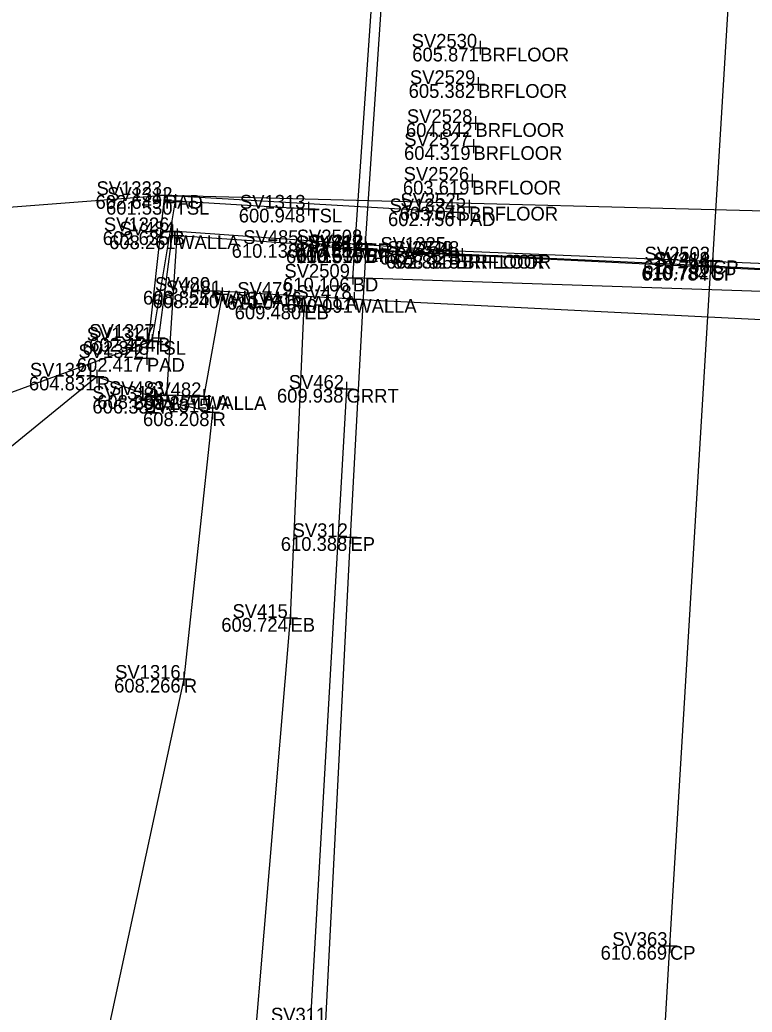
# Model space of a CAD drawing. Extents: x -2 to 1979875, y -2 to 232027.
# Drawn here: x 1978749.24 to 1978775.86, y 231225.36 to 231261.41 of the extents above; entities that cross this region are included whole.
import ezdxf

# ---------------------------------------------------------------- set-up
doc = ezdxf.new("R2010")
doc.units = 0
for name, color, linetype in [('_CIVIL_CONSTRUCTION', 7, 'Continuous'), ('BR_X_SV_Abut', 7, 'Continuous'), ('BR_X_SV_Deck_Floor_Text', 7, 'Continuous'), ('BR_X_SV_Deck_Top', 7, 'Continuous'), ('BR_X_SV_Deck_Top_Text', 7, 'Continuous'), ('DR_X_Erosion_Control', 7, 'Continuous'), ('GE_P_Alignment', 7, 'Continuous'), ('GE_P_Alignment_1000_Stations', 7, 'Continuous'), ('GE_P_Alignment_500_Stations', 7, 'Continuous'), ('GE_X_Alignment', 7, 'Continuous'), ('GE_X_Alignment_1000_Curve_Data', 7, 'Continuous'), ('GE_X_Alignment_1000_Stations', 7, 'Continuous'), ('GE_X_Alignment_100_Curve_Data', 7, 'Continuous'), ('GE_X_Alignment_100_Stations', 7, 'Continuous'), ('HY_X_Water_Edge', 7, 'Continuous'), ('RD_X_Concrete_Pad', 7, 'Continuous'), ('SC_Scratch1', 7, 'Continuous'), ('SV_X_Toe_of_Slope', 7, 'Continuous')]:
    doc.layers.add(name, color=color, linetype=linetype)

msp = doc.modelspace()

# ---------------------------------------------------------------- linework, layer by layer
at = {"layer": 'BR_X_SV_Abut'}
for p, q in [((1978761.383, 231253.071), (1978785.768, 231251.859)), ((1978761.397, 231251.268), (1978785.698, 231250.046))]:
    msp.add_line(p, q, dxfattribs=at)
msp.add_lwpolyline([(1978761.397, 231251.268), (1978759.239, 231251.381), (1978756.252, 231251.566), (1978756.595, 231251.439), (1978755.933, 231247.737), (1978754.58, 231247.78), (1978754.956, 231253.581), (1978759.469, 231253.268), (1978761.383, 231253.071)], dxfattribs=at)
at = {"layer": 'BR_X_SV_Deck_Top'}
msp.add_lwpolyline([(1978761.339, 231252.043), (1978764.257, 231294.289), (1978788.348, 231293.277), (1978785.624, 231251.227)], close=True, dxfattribs=at)
at = {"layer": 'DR_X_Erosion_Control'}
msp.add_lwpolyline([(1978754.349, 231247.608), (1978756.246, 231247.151), (1978755.199, 231237.468), (1978752.104, 231223.077), (1978746.455, 231220.249), (1978747.402, 231233.48), (1978747.083, 231244.422), (1978752.039, 231248.449)], close=True, dxfattribs=at)
at = {"layer": 'GE_P_Alignment'}
msp.add_line((1978782.12, 231252.312), (1978764.845, 231253.02), dxfattribs=at)
for points in [[(1978764.845, 231253.02), (1978754.789, 231253.731), (1978754.276, 231249.856)], [(1978761.807, 231253.072), (1978774.411, 231252.478), (1978785.5, 231251.852)]]:
    msp.add_lwpolyline(points, dxfattribs=at)
at = {"layer": 'GE_P_Alignment_1000_Stations'}
msp.add_lwpolyline([(1978761.115, 231248.004), (1978759.735, 231223.843), (1978758.381, 231198.86), (1978756.732, 231174.726), (1978755.587, 231155.241), (1978753.463, 231135.535), (1978751.71, 231124.03)], dxfattribs=at)
at = {"layer": 'GE_X_Alignment_1000_Curve_Data'}
for points in [[(1978774.433, 231252.669), (1978775.92, 231277.185), (1978776.918, 231292.992)], [(1978759.598, 230998.872), (1978761.121, 231023.464), (1978762.432, 231045.872), (1978763.634, 231067.205), (1978765.062, 231090.264), (1978766.176, 231112.831), (1978767.489, 231135.467), (1978768.77, 231157.711), (1978770.096, 231180.642), (1978771.565, 231205.428), (1978772.87, 231227.762), (1978774.351, 231252.439)]]:
    msp.add_lwpolyline(points, dxfattribs=at)
at = {"layer": 'GE_X_Alignment_1000_Stations'}
for points in [[(1978764.365, 231293.633), (1978762.994, 231271.213), (1978761.795, 231253.289)], [(1978748.464, 231019.612), (1978749.988, 231043.472), (1978751.447, 231065.273), (1978752.63, 231084.658), (1978753.33, 231098.021), (1978753.711, 231111.371), (1978754.899, 231133.583), (1978756.265, 231155.604), (1978757.703, 231177.553), (1978759.075, 231200.883), (1978760.359, 231225.015), (1978761.255, 231242.617), (1978761.827, 231253.108)]]:
    msp.add_lwpolyline(points, dxfattribs=at)
at = {"layer": 'GE_X_Alignment_100_Curve_Data'}
for p, q in [((1978765.723, 231260.401), (1978766.223, 231260.401)), ((1978765.973, 231260.651), (1978765.973, 231260.151)), ((1978765.973, 231260.401), (1978765.973, 231260.401)), ((1978765.9, 231259.328), (1978765.9, 231258.828)), ((1978765.65, 231259.078), (1978766.15, 231259.078)), ((1978765.9, 231259.078), (1978765.9, 231259.078)), ((1978765.801, 231257.911), (1978765.801, 231257.411)), ((1978765.551, 231257.661), (1978766.051, 231257.661)), ((1978765.801, 231257.661), (1978765.801, 231257.661)), ((1978765.726, 231257.071), (1978765.726, 231256.571)), ((1978765.476, 231256.821), (1978765.976, 231256.821)), ((1978765.726, 231256.821), (1978765.726, 231256.821)), ((1978765.684, 231255.815), (1978765.684, 231255.315)), ((1978754.512, 231255.296), (1978754.512, 231254.796)), ((1978765.434, 231255.565), (1978765.934, 231255.565)), ((1978765.684, 231255.565), (1978765.684, 231255.565)), ((1978754.262, 231255.046), (1978754.762, 231255.046)), ((1978754.512, 231255.046), (1978754.512, 231255.046)), ((1978754.902, 231255.083), (1978754.902, 231254.583)), ((1978754.652, 231254.833), (1978755.152, 231254.833)), ((1978754.902, 231254.833), (1978754.902, 231254.833)), ((1978759.478, 231254.551), (1978759.978, 231254.551)), ((1978759.728, 231254.801), (1978759.728, 231254.301)), ((1978759.728, 231254.551), (1978759.728, 231254.551)), ((1978765.155, 231254.669), (1978765.155, 231254.169)), ((1978765.321, 231254.62), (1978765.821, 231254.62)), ((1978765.571, 231254.87), (1978765.571, 231254.37)), ((1978765.571, 231254.62), (1978765.571, 231254.62)), ((1978764.905, 231254.419), (1978765.405, 231254.419)), ((1978765.155, 231254.419), (1978765.155, 231254.419)), ((1978754.789, 231253.981), (1978754.789, 231253.481)), ((1978754.956, 231253.831), (1978754.956, 231253.331)), ((1978754.539, 231253.731), (1978755.039, 231253.731)), ((1978754.706, 231253.581), (1978755.206, 231253.581)), ((1978754.789, 231253.731), (1978754.789, 231253.731)), ((1978754.956, 231253.581), (1978754.956, 231253.581)), ((1978759.469, 231253.518), (1978759.469, 231253.018)), ((1978761.795, 231253.539), (1978761.795, 231253.039)), ((1978759.219, 231253.268), (1978759.719, 231253.268)), ((1978759.469, 231253.268), (1978759.469, 231253.268)), ((1978761.383, 231253.321), (1978761.383, 231252.821)), ((1978761.545, 231253.289), (1978762.045, 231253.289)), ((1978761.577, 231253.108), (1978762.077, 231253.108)), ((1978761.795, 231253.289), (1978761.795, 231253.289)), ((1978761.807, 231253.322), (1978761.807, 231252.822)), ((1978761.827, 231253.358), (1978761.827, 231252.858)), ((1978761.827, 231253.108), (1978761.827, 231253.108)), ((1978764.845, 231253.27), (1978764.845, 231252.77)), ((1978765.083, 231253.123), (1978765.083, 231252.623)), ((1978765.323, 231253.121), (1978765.323, 231252.621)), ((1978761.133, 231253.071), (1978761.633, 231253.071)), ((1978761.383, 231253.071), (1978761.383, 231253.071)), ((1978761.557, 231253.072), (1978762.057, 231253.072)), ((1978761.807, 231253.072), (1978761.807, 231253.072)), ((1978764.595, 231253.02), (1978765.095, 231253.02)), ((1978764.833, 231252.873), (1978765.333, 231252.873)), ((1978764.845, 231253.02), (1978764.845, 231253.02)), ((1978765.073, 231252.871), (1978765.573, 231252.871)), ((1978765.083, 231252.873), (1978765.083, 231252.873)), ((1978765.323, 231252.871), (1978765.323, 231252.871)), ((1978774.433, 231252.919), (1978774.433, 231252.419)), ((1978774.101, 231252.439), (1978774.601, 231252.439)), ((1978774.161, 231252.478), (1978774.661, 231252.478)), ((1978774.183, 231252.669), (1978774.683, 231252.669)), ((1978774.351, 231252.689), (1978774.351, 231252.189)), ((1978774.351, 231252.439), (1978774.351, 231252.439)), ((1978774.411, 231252.728), (1978774.411, 231252.228)), ((1978774.411, 231252.478), (1978774.411, 231252.478)), ((1978774.433, 231252.669), (1978774.433, 231252.669)), ((1978761.089, 231252.043), (1978761.589, 231252.043)), ((1978761.339, 231252.293), (1978761.339, 231251.793)), ((1978761.339, 231252.043), (1978761.339, 231252.043)), ((1978756.252, 231251.816), (1978756.252, 231251.316)), ((1978756.595, 231251.689), (1978756.595, 231251.189)), ((1978756.002, 231251.566), (1978756.502, 231251.566)), ((1978756.252, 231251.566), (1978756.252, 231251.566)), ((1978756.345, 231251.439), (1978756.845, 231251.439)), ((1978756.595, 231251.439), (1978756.595, 231251.439)), ((1978758.989, 231251.381), (1978759.489, 231251.381)), ((1978759.239, 231251.631), (1978759.239, 231251.131)), ((1978759.239, 231251.381), (1978759.239, 231251.381)), ((1978761.397, 231251.518), (1978761.397, 231251.018)), ((1978759.33, 231251.031), (1978759.83, 231251.031)), ((1978759.58, 231251.281), (1978759.58, 231250.781)), ((1978759.58, 231251.031), (1978759.58, 231251.031)), ((1978761.147, 231251.268), (1978761.647, 231251.268)), ((1978761.397, 231251.268), (1978761.397, 231251.268)), ((1978754.026, 231249.856), (1978754.526, 231249.856)), ((1978754.051, 231249.994), (1978754.051, 231249.494)), ((1978754.276, 231250.106), (1978754.276, 231249.606)), ((1978754.276, 231249.856), (1978754.276, 231249.856)), ((1978753.801, 231249.744), (1978754.301, 231249.744)), ((1978754.051, 231249.744), (1978754.051, 231249.744)), ((1978753.86, 231249.374), (1978753.86, 231248.874)), ((1978753.61, 231249.124), (1978754.11, 231249.124)), ((1978753.86, 231249.124), (1978753.86, 231249.124)), ((1978751.789, 231248.449), (1978752.289, 231248.449)), ((1978752.039, 231248.699), (1978752.039, 231248.199)), ((1978752.039, 231248.449), (1978752.039, 231248.449)), ((1978761.115, 231248.254), (1978761.115, 231247.754)), ((1978754.33, 231247.78), (1978754.83, 231247.78)), ((1978754.349, 231247.858), (1978754.349, 231247.358)), ((1978754.58, 231248.03), (1978754.58, 231247.53)), ((1978754.58, 231247.78), (1978754.58, 231247.78)), ((1978755.683, 231247.737), (1978756.183, 231247.737)), ((1978755.933, 231247.987), (1978755.933, 231247.487)), ((1978755.933, 231247.737), (1978755.933, 231247.737)), ((1978760.865, 231248.004), (1978761.365, 231248.004)), ((1978761.115, 231248.004), (1978761.115, 231248.004)), ((1978754.099, 231247.608), (1978754.599, 231247.608)), ((1978754.349, 231247.608), (1978754.349, 231247.608)), ((1978756.246, 231247.401), (1978756.246, 231246.901)), ((1978755.996, 231247.151), (1978756.496, 231247.151)), ((1978756.246, 231247.151), (1978756.246, 231247.151)), ((1978761.255, 231242.867), (1978761.255, 231242.367)), ((1978761.005, 231242.617), (1978761.505, 231242.617)), ((1978761.255, 231242.617), (1978761.255, 231242.617)), ((1978759.078, 231239.929), (1978759.078, 231239.429)), ((1978758.828, 231239.679), (1978759.328, 231239.679)), ((1978759.078, 231239.679), (1978759.078, 231239.679)), ((1978755.199, 231237.718), (1978755.199, 231237.218)), ((1978754.949, 231237.468), (1978755.449, 231237.468)), ((1978755.199, 231237.468), (1978755.199, 231237.468)), ((1978772.87, 231228.012), (1978772.87, 231227.512)), ((1978772.62, 231227.762), (1978773.12, 231227.762)), ((1978772.87, 231227.762), (1978772.87, 231227.762))]:
    msp.add_line(p, q, dxfattribs=at)
at = {"layer": 'HY_X_Water_Edge'}
msp.add_lwpolyline([(1978710.396, 231262.363), (1978725.371, 231260.246), (1978739.363, 231256.715), (1978742.039, 231254.081), (1978754.512, 231255.046), (1978783.289, 231254.287), (1978787.737, 231256.586), (1978799.967, 231256.811), (1978817.09, 231257.737), (1978832.082, 231262.479)], dxfattribs=at)
at = {"layer": 'RD_X_Concrete_Pad'}
msp.add_lwpolyline([(1978753.86, 231249.124), (1978754.512, 231255.046), (1978765.155, 231254.419)], dxfattribs=at)
at = {"layer": 'SC_Scratch1'}
msp.add_lwpolyline([(1978745.216, 230999.029), (1978746.767, 231023.392), (1978748.222, 231047.741), (1978749.82, 231072.495), (1978750.429, 231094.309), (1978750.937, 231113.218), (1978752.038, 231133.252), (1978754.204, 231154.655), (1978755.357, 231179.613), (1978756.841, 231203.041), (1978757.548, 231221.462), (1978759.078, 231239.679), (1978759.58, 231251.031)], dxfattribs=at)
at = {"layer": 'SV_X_Toe_of_Slope'}
msp.add_lwpolyline([(1978747.448, 231227.335), (1978746.946, 231238.338), (1978747.673, 231247.419), (1978754.051, 231249.744), (1978754.902, 231254.833), (1978759.728, 231254.551)], dxfattribs=at)

# ---------------------------------------------------------------- texts
at = {"layer": '_CIVIL_CONSTRUCTION'}
for s, p in [('602.649', (1978751.991, 231254.546)), ('601.530', (1978752.372, 231254.333)), ('600.948', (1978757.198, 231254.051)), ('602.756', (1978762.623, 231253.919)), ('602.635', (1978752.254, 231253.231)), ('610.557', (1978759.244, 231252.789)), ('610.539', (1978759.306, 231252.608)), ('610.515', (1978759.272, 231252.572)), ('602.782', (1978762.317, 231252.52)), ('610.784', (1978771.835, 231251.939)), ('610.782', (1978771.883, 231251.978)), ('610.790', (1978771.903, 231252.169)), ('609.480', (1978757.05, 231250.531)), ('602.474', (1978751.76, 231249.356)), ('602.348', (1978751.521, 231249.244)), ('602.417', (1978751.309, 231248.624)), ('604.831', (1978749.569, 231247.949)), ('609.938', (1978758.585, 231247.504)), ('606.331', (1978751.879, 231247.108)), ('608.208', (1978753.716, 231246.651)), ('610.388', (1978758.725, 231242.117)), ('609.724', (1978756.562, 231239.179)), ('608.266', (1978752.667, 231236.968)), ('610.669', (1978770.349, 231227.262))]:
    msp.add_text(s, height=0.5, dxfattribs=at).set_placement(p)
at = {"layer": 'BR_X_SV_Deck_Floor_Text'}
for s, p in [('SV2530', (1978763.481, 231260.401)), ('605.871', (1978763.503, 231259.901)), ('BRFLOOR', (1978765.973, 231259.901)), ('SV2529', (1978763.418, 231259.078)), ('605.382', (1978763.372, 231258.578)), ('BRFLOOR', (1978765.9, 231258.578)), ('SV2528', (1978763.31, 231257.661)), ('604.842', (1978763.273, 231257.161)), ('BRFLOOR', (1978765.801, 231257.161)), ('SV2527', (1978763.213, 231256.821)), ('604.319', (1978763.205, 231256.321)), ('BRFLOOR', (1978765.726, 231256.321)), ('SV2526', (1978763.19, 231255.565)), ('603.619', (1978763.163, 231255.065)), ('BRFLOOR', (1978765.684, 231255.065)), ('SV2525', (1978763.074, 231254.62)), ('603.043', (1978763.046, 231254.12)), ('BRFLOOR', (1978765.571, 231254.12)), ('SV2549', (1978762.601, 231252.873)), ('SV2548', (1978762.832, 231252.871)), ('602.885', (1978762.548, 231252.373)), ('608.315', (1978762.788, 231252.371)), ('BRFLOOR', (1978765.083, 231252.373)), ('BRFLOOR', (1978765.323, 231252.371))]:
    msp.add_text(s, height=0.5, dxfattribs=at).set_placement(p)
at = {"layer": 'BR_X_SV_Deck_Top_Text'}
for s, p in [('SV2509', (1978758.857, 231252.043)), ('610.106', (1978758.807, 231251.543)), ('BD', (1978761.339, 231251.543))]:
    msp.add_text(s, height=0.5, dxfattribs=at).set_placement(p)
at = {"layer": 'GE_P_Alignment_500_Stations'}
for s, p in [('SV484', (1978752.867, 231253.581)), ('608.261', (1978752.486, 231253.081)), ('WALLA', (1978754.956, 231253.081)), ('SV485', (1978757.36, 231253.268)), ('SV486', (1978759.278, 231253.071)), ('610.138', (1978756.939, 231252.768)), ('WALLA', (1978759.469, 231252.768)), ('610.161', (1978758.913, 231252.571)), ('WALLA', (1978761.383, 231252.571)), ('SV480', (1978754.148, 231251.566)), ('SV481', (1978754.552, 231251.439)), ('SV479', (1978757.145, 231251.381)), ('SV478', (1978759.294, 231251.268)), ('608.855', (1978753.717, 231251.066)), ('608.240', (1978754.065, 231250.939)), ('WALLA', (1978756.252, 231251.066)), ('WALLA', (1978756.595, 231250.939)), ('610.071', (1978756.769, 231250.881)), ('WALLA', (1978759.239, 231250.881)), ('610.091', (1978758.927, 231250.768)), ('WALLA', (1978761.397, 231250.768)), ('SV483', (1978752.482, 231247.78)), ('SV482', (1978753.832, 231247.737)), ('608.282', (1978752.052, 231247.28)), ('608.257', (1978753.382, 231247.237)), ('WALLA', (1978754.58, 231247.28)), ('WALLA', (1978755.933, 231247.237))]:
    msp.add_text(s, height=0.5, dxfattribs=at).set_placement(p)
at = {"layer": 'GE_X_Alignment'}
for s, p in [('SV1323', (1978752.026, 231255.046)), ('SV1312', (1978752.412, 231254.833)), ('SV1313', (1978757.242, 231254.551)), ('SV1324', (1978762.678, 231254.419)), ('SV1326', (1978752.295, 231253.731)), ('SV2508', (1978759.304, 231253.289)), ('SV417', (1978759.682, 231253.072)), ('SV313', (1978759.729, 231253.108)), ('SV1325', (1978762.348, 231253.02)), ('SV2503', (1978771.947, 231252.669)), ('SV364', (1978772.262, 231252.439)), ('SV418', (1978772.308, 231252.478)), ('SV416', (1978757.475, 231251.031)), ('SV1311', (1978751.671, 231249.744)), ('SV1327', (1978751.763, 231249.856)), ('SV1322', (1978751.37, 231249.124)), ('SV1321', (1978749.607, 231248.449)), ('SV462', (1978759.014, 231248.004)), ('SV1314', (1978751.872, 231247.608)), ('SV1315', (1978753.749, 231247.151)), ('SV312', (1978759.154, 231242.617)), ('SV415', (1978756.969, 231239.679)), ('SV1316', (1978752.705, 231237.468)), ('SV363', (1978770.772, 231227.762)), ('SV311', (1978758.367, 231225.015))]:
    msp.add_text(s, height=0.5, dxfattribs=at).set_placement(p)
at = {"layer": 'GE_X_Alignment_100_Stations'}
for s, p in [('PAD', (1978754.512, 231254.546)), ('TSL', (1978754.902, 231254.333)), ('TSL', (1978759.728, 231254.051)), ('PAD', (1978765.155, 231253.919)), ('B', (1978754.789, 231253.231)), ('EP', (1978761.795, 231252.789)), ('EP', (1978761.827, 231252.608)), ('B', (1978761.807, 231252.572)), ('B', (1978764.845, 231252.52)), ('CP', (1978774.351, 231251.939)), ('B', (1978774.411, 231251.978)), ('CP', (1978774.433, 231252.169)), ('EB', (1978759.58, 231250.531)), ('B', (1978754.276, 231249.356)), ('TSL', (1978754.051, 231249.244)), ('PAD', (1978753.86, 231248.624)), ('R', (1978752.039, 231247.949)), ('GRRT', (1978761.115, 231247.504)), ('R', (1978754.349, 231247.108)), ('R', (1978756.246, 231246.651)), ('EP', (1978761.255, 231242.117)), ('EB', (1978759.078, 231239.179)), ('R', (1978755.199, 231236.968)), ('CP', (1978772.87, 231227.262))]:
    msp.add_text(s, height=0.5, dxfattribs=at).set_placement(p)

doc.saveas('drawing.dxf')
